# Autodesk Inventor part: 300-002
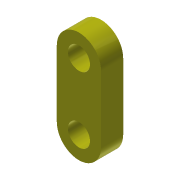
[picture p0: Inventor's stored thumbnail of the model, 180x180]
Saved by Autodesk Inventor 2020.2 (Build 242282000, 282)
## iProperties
Created: 2014-01
Part Number: 300-002
Material: Ogólny
Document SubType Name: Modeling
Designer: F.Stasiak
Density: 1 g/cm^3
Appearance: Żółta
Manager: www.cadconsulting.pl
Company: Fabian Stasiak CAD Consulting
Author: F.Stasiak
Subject: Zbiór ćwiczeń. Autodesk Inventor 2020. Kurs podstawowy
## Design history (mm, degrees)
sketch "Szkic1"
  geometry: L1 (0, 0)-(0, 30); L2 (10, 0)-(10, 30); L3 (-10, 30)-(-10, 0); C1 r 5 at (0, 30); C2 r 5 at (0, 0); A1 r 10 centre (0, 0) between (-10, 0) and (10, 0); A2 r 10 centre (0, 30) between (10, 30) and (-10, 30); 1 further point
  constraints: 8 end point, 4 centre point, 4 point on circle, 4 tangent, 2 coincident, 1 midpoint, 1 parallel, 1 vertical
  dimensions: "d0" = 30 distance of L1.start L1.end; "d1" = 20 diameter of A2; "d2" = 10 diameter of C1; "d3" = 10 diameter of C2
extrude "Wyciągnięcie proste1" new body sketch "Szkic1" distance "d4" = 10; taper "d5" = 0 deg
node "Bryła1"
